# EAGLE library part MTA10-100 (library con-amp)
AMP connector
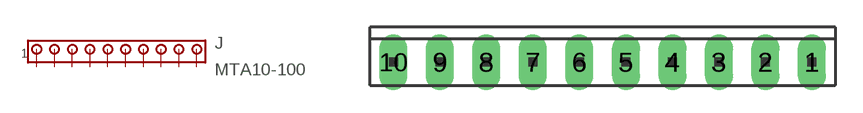
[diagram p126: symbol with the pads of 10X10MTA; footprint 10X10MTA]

Designator prefix J

## MTA10-100 (OC_FARNELL: unknown; OC_NEWARK: unknown)  [10X10MTA]
1  1  pas
2  2  pas
3  3  pas
4  4  pas
5  5  pas
6  6  pas
7  7  pas
8  8  pas
9  9  pas
10  10  pas

## Footprint 10X10MTA (pad centres in mm)
AMP MTA connector Source: http://ecommas.tycoelectronics.com .. ENG_CD_640456_W.pdf
drill 1.016 long: 1 11.43,0; 2 8.89,0; 3 6.35,0; 4 3.81,0; 5 1.27,0; 6 -1.27,0; 7 -3.81,0; 8 -6.35,0; 9 -8.89,0; 10 -11.43,0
